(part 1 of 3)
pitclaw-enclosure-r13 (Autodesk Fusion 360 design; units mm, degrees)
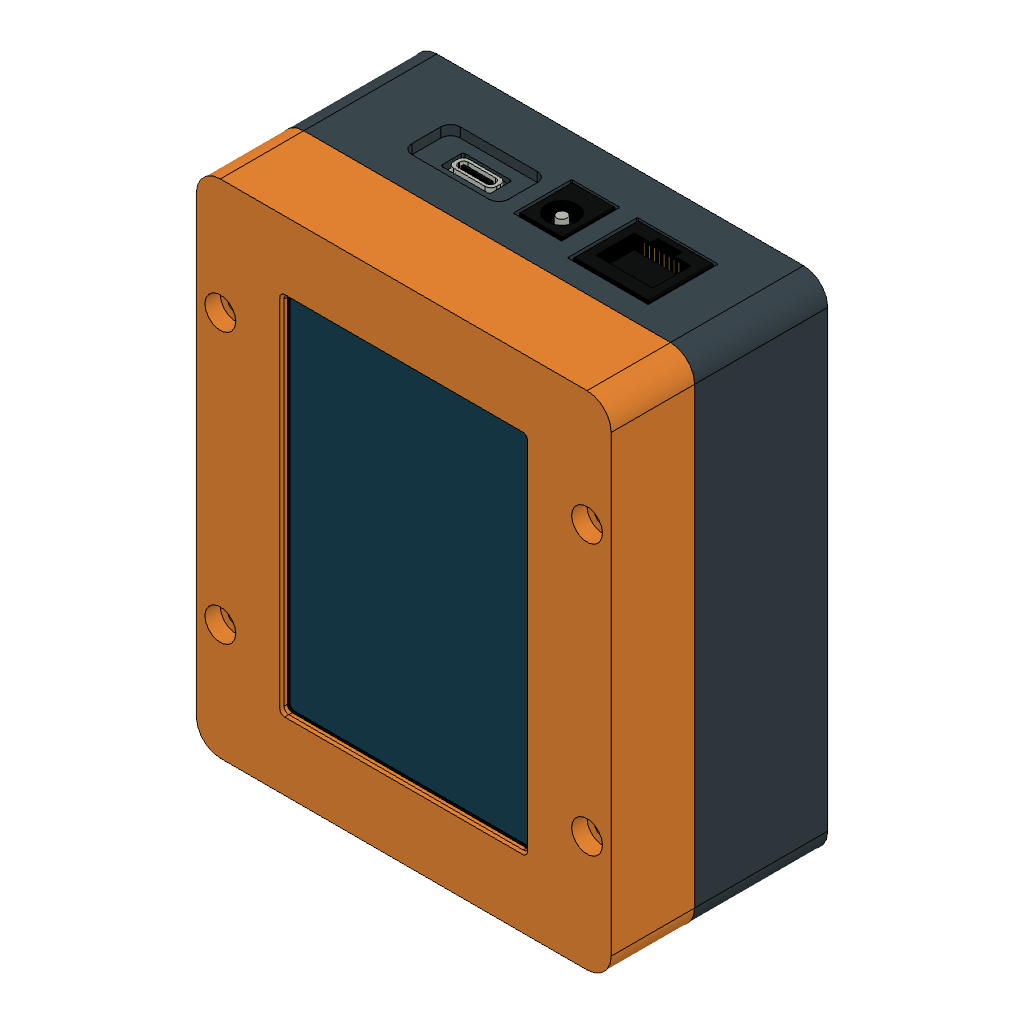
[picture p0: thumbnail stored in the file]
description: Part Number
part number: D_DO-41_SOD81_P10.16mm_Horizontal
part number: R_Axial_DIN0207_L6.3mm_D2.5mm_P7.62mm_Horizontal
part number: PinHeader_1x02_P2.54mm_Vertical
part number: TO-92_Inline_Wide
part number: JST_XH_B2B-XH-A_1x02_P2.50mm_Vertical
part number: JST_XH_B8B-XH-A_1x08_P2.50mm_Vertical
part number: pitclaw-carrier_pad
part number: pitclaw-carrier_silkscreen
part number: pitclaw-carrier_soldermask
parameter "floor_t" = 2.5 comment "PitClaw r8 nominal assembly datum; recheck fit after editing"
parameter "carrier_standoff" = 5 comment "PitClaw r8 nominal assembly datum; recheck fit after editing"
parameter "seam_z" = 27.6 comment "PitClaw r8 nominal assembly datum; recheck fit after editing"
parameter "case_h" = 44.9 comment "PitClaw r8 nominal assembly datum; recheck fit after editing"
parameter "retainer_t" = 2.5 comment "PitClaw r8 nominal assembly datum; recheck fit after editing"
parameter "retainer_top" = 34.4 (= "screen_front_z - screen_mount_depth") comment "PitClaw r8 nominal assembly datum; recheck fit after editing"
parameter "retainer_bottom" = 31.9 (= "retainer_top - retainer_t") comment "PitClaw r8 nominal assembly datum; recheck fit after editing"
parameter "insert_pilot" = 4.2 comment "PitClaw r8 nominal assembly datum; recheck fit after editing"
parameter "insert_depth" = 5 comment "PitClaw r8 nominal assembly datum; recheck fit after editing"
parameter "lip_h" = 2 comment "PitClaw r8 nominal assembly datum; recheck fit after editing"
parameter "bezel_contact_z" = 43.7 comment "Fixed underside of the bezel, on the inactive glass border"
parameter "screen_mount_depth" = 9.3
parameter "screen_interface_t" = 0 comment "Direct glass contact; no assumed soft strip or open air gap"
parameter "screen_front_z" = 43.7 (= "bezel_contact_z - screen_interface_t") comment "Screen front follows the bezel contact face"
parameter "retainer_stop_z" = 34.4 comment "Fixed shell stop: original32.6 plus1.8mm correction"
sketch "Outer shell profile" plane through (0, 0, 0) normal (0, 0, 1) x axis (1, 0, 0)
  line L1 (38, -52) -> (-38, -52)
  line L2 (43, 47) -> (43, -47)
  line L3 (-38, 52) -> (38, 52)
  line L4 (-43, -47) -> (-43, 47)
  arc A1 centre (38, -47) radius 5 clockwise from (43, -47) to (38, -52)
  arc A2 centre (38, 47) radius 5 clockwise from (38, 52) to (43, 47)
  arc A3 centre (-38, 47) radius 5 clockwise from (-43, 47) to (-38, 52)
  arc A4 centre (-38, -47) radius 5 clockwise from (-38, -52) to (-43, -47)
extrude "Extrude1" new body sketch "Outer shell profile" along normal blind 27.6 (= "seam_z") bodies "01 Bottom shell"
sketch "Open cavity profile" plane through (0, 0, 0) normal (0, 0, 1) x axis (1, 0, 0)
  line L1 (38, -49.5) -> (-38, -49.5)
  line L2 (40.5, 47) -> (40.5, -47)
  line L3 (-38, 49.5) -> (38, 49.5)
  line L4 (-40.5, -47) -> (-40.5, 47)
  arc A1 centre (38, -47) radius 2.5 clockwise from (40.5, -47) to (38, -49.5)
  arc A2 centre (38, 47) radius 2.5 clockwise from (38, 49.5) to (40.5, 47)
  arc A3 centre (-38, 47) radius 2.5 clockwise from (-40.5, 47) to (-38, 49.5)
  arc A4 centre (-38, -47) radius 2.5 clockwise from (-38, -49.5) to (-40.5, -47)
extrude "Extrude2" cut sketch "Open cavity profile" blind 27.6 (= "seam_z") from offset 2.5 (= "floor_t")
sketch "Four carrier insert bosses profile" plane through (0, 0, 0) normal (0, 0, 1) x axis (1, 0, 0)
  circle C1 centre (-25.5, -37) radius 4.5
  circle C2 centre (-25.5, 21) radius 4.5
  circle C3 centre (25.5, -37) radius 4.5
  circle C4 centre (25.5, 21) radius 4.5
extrude "Extrude3" add sketch "Four carrier insert bosses profile" blind 5 (= "carrier_standoff") from offset 2.5 (= "floor_t")
sketch "Four case closure columns profile" plane through (0, 0, 0) normal (0, 0, 1) x axis (1, 0, 0)
  circle C1 centre (-38, -28) radius 4.5
  circle C2 centre (-38, 28) radius 4.5
  circle C3 centre (38, -28) radius 4.5
  circle C4 centre (38, 28) radius 4.5
extrude "Extrude4" add sketch "Four case closure columns profile" blind 25.1 (= "seam_z - floor_t") from offset 2.5 (= "floor_t")
sketch "USB recess internal backing profile" plane through (0, 0, 0) normal (0, 1, 0) x axis (1, 0, 0)
  line L1 (22.5, -10.7) -> (6.5, -10.7)
  line L2 (24.5, -18.7) -> (24.5, -12.7)
  line L3 (6.5, -20.7) -> (22.5, -20.7)
  line L4 (4.5, -12.7) -> (4.5, -18.7)
  arc A1 centre (22.5, -12.7) radius 2 clockwise from (22.5, -10.7) to (24.5, -12.7)
  arc A2 centre (22.5, -18.7) radius 2 clockwise from (24.5, -18.7) to (22.5, -20.7)
  arc A3 centre (6.5, -18.7) radius 2 clockwise from (6.5, -20.7) to (4.5, -18.7)
  arc A4 centre (6.5, -12.7) radius 2 clockwise from (4.5, -12.7) to (6.5, -10.7)
extrude "Extrude5" add sketch "USB recess internal backing profile" blind 1.02 from offset 48.5
sketch "Carrier insert pilots profile" plane through (0, 0, 0) normal (0, 0, 1) x axis (1, 0, 0)
  circle C1 centre (-25.5, -37) radius 2.1
  circle C2 centre (-25.5, 21) radius 2.1
  circle C3 centre (25.5, -37) radius 2.1
  circle C4 centre (25.5, 21) radius 2.1
  dimension "d127" diameter C1 = 4.2 (= "insert_pilot")
  dimension "d128" diameter C2 = 4.2 (= "insert_pilot")
  dimension "d129" diameter C3 = 4.2 (= "insert_pilot")
  dimension "d130" diameter C4 = 4.2 (= "insert_pilot")
extrude "Extrude6" cut sketch "Carrier insert pilots profile" blind 5.02 from offset 2.5 (= "floor_t")
sketch "Closure insert pilots profile" plane through (0, 0, 0) normal (0, 0, 1) x axis (1, 0, 0)
  circle C1 centre (-38, -28) radius 2.1
  circle C2 centre (-38, 28) radius 2.1
  circle C3 centre (38, -28) radius 2.1
  circle C4 centre (38, 28) radius 2.1
  dimension "d131" diameter C1 = 4.2 (= "insert_pilot")
  dimension "d132" diameter C2 = 4.2 (= "insert_pilot")
  dimension "d133" diameter C3 = 4.2 (= "insert_pilot")
  dimension "d134" diameter C4 = 4.2 (= "insert_pilot")
extrude "Extrude7" cut sketch "Closure insert pilots profile" blind 5.02 from offset 22.6 (= "seam_z - insert_depth")
sketch "Three probe access holes profile" plane through (0, 0, 0) normal (0, 1, 0) x axis (1, 0, 0)
  circle C1 centre (-17, -11.65) radius 5.25
  circle C2 centre (0, -11.65) radius 5.25
  circle C3 centre (17, -11.65) radius 5.25
extrude "Extrude8" cut sketch "Three probe access holes profile" blind 10 from offset -57
sketch "RJ45 fitted opening profile" plane through (0, 0, 0) normal (0, 1, 0) x axis (1, 0, 0)
  line L1 (-12.325, -8.6) -> (-28.675, -8.6)
  line L2 (-12.125, -22.91) -> (-12.125, -8.8)
  line L3 (-28.675, -23.11) -> (-12.325, -23.11)
  line L4 (-28.875, -8.8) -> (-28.875, -22.91)
  arc A1 centre (-12.325, -8.8) radius 0.2 clockwise from (-12.325, -8.6) to (-12.125, -8.8)
  arc A2 centre (-12.325, -22.91) radius 0.2 clockwise from (-12.125, -22.91) to (-12.325, -23.11)
  arc A3 centre (-28.675, -22.91) radius 0.2 clockwise from (-28.675, -23.11) to (-28.875, -22.91)
  arc A4 centre (-28.675, -8.8) radius 0.2 clockwise from (-28.875, -8.8) to (-28.675, -8.6)
extrude "Extrude9" cut sketch "RJ45 fitted opening profile" blind 10 from offset 47
sketch "Barrel fitted opening profile" plane through (0, 0, 0) normal (0, 1, 0) x axis (1, 0, 0)
  line L1 (1.3, -8.6) -> (-8.3, -8.6)
  line L2 (1.5, -20.5) -> (1.5, -8.8)
  line L3 (-8.3, -20.7) -> (1.3, -20.7)
  line L4 (-8.5, -8.8) -> (-8.5, -20.5)
  arc A1 centre (1.3, -8.8) radius 0.2 clockwise from (1.3, -8.6) to (1.5, -8.8)
  arc A2 centre (1.3, -20.5) radius 0.2 clockwise from (1.5, -20.5) to (1.3, -20.7)
  arc A3 centre (-8.3, -20.5) radius 0.2 clockwise from (-8.3, -20.7) to (-8.5, -20.5)
  arc A4 centre (-8.3, -8.8) radius 0.2 clockwise from (-8.5, -8.8) to (-8.3, -8.6)
extrude "Extrude10" cut sketch "Barrel fitted opening profile" blind 10 from offset 47
sketch "USB fitted shell aperture profile" plane through (0, 0, 0) normal (0, 1, 0) x axis (1, 0, 0)
  line L1 (19.17, -13) -> (9.83, -13)
  line L2 (19.57, -17.3) -> (19.57, -13.4)
  line L3 (9.83, -17.7) -> (19.17, -17.7)
  line L4 (9.43, -13.4) -> (9.43, -17.3)
  arc A1 centre (19.17, -13.4) radius 0.4 clockwise from (19.17, -13) to (19.57, -13.4)
  arc A2 centre (19.17, -17.3) radius 0.4 clockwise from (19.57, -17.3) to (19.17, -17.7)
  arc A3 centre (9.83, -17.3) radius 0.4 clockwise from (9.83, -17.7) to (9.43, -17.3)
  arc A4 centre (9.83, -13.4) radius 0.4 clockwise from (9.43, -13.4) to (9.83, -13)
extrude "Extrude11" cut sketch "USB fitted shell aperture profile" blind 10 from offset 47
sketch "USB shallow external recess profile" plane through (0, 0, 0) normal (0, 1, 0) x axis (1, 0, 0)
  line L1 (22.5, -10.7) -> (6.5, -10.7)
  line L2 (24.5, -18.7) -> (24.5, -12.7)
  line L3 (6.5, -20.7) -> (22.5, -20.7)
  line L4 (4.5, -12.7) -> (4.5, -18.7)
  arc A1 centre (22.5, -12.7) radius 2 clockwise from (22.5, -10.7) to (24.5, -12.7)
  arc A2 centre (22.5, -18.7) radius 2 clockwise from (24.5, -18.7) to (22.5, -20.7)
  arc A3 centre (6.5, -18.7) radius 2 clockwise from (6.5, -20.7) to (4.5, -18.7)
  arc A4 centre (6.5, -12.7) radius 2 clockwise from (4.5, -12.7) to (6.5, -10.7)
extrude "Extrude12" cut sketch "USB shallow external recess profile" blind 2.02 from offset 50
sketch "Hidden carrier edge channel profile" plane through (0, 0, 0) normal (0, 0, 1) x axis (1, 0, 0)
  line L1 (30.5, 49.48) -> (-30.5, 49.48)
  line L2 (30.5, 51) -> (30.5, 49.48)
  line L3 (-30.5, 51) -> (30.5, 51)
  line L4 (-30.5, 49.48) -> (-30.5, 51)
extrude "Extrude13" cut sketch "Hidden carrier edge channel profile" blind 2.9 from offset 7
sketch "Hidden USB PCB edge clearance profile" plane through (0, 0, 0) normal (0, 0, 1) x axis (1, 0, 0)
  line L1 (24.86, 48.48) -> (4.14, 48.48)
  line L2 (24.86, 49.057) -> (24.86, 48.48)
  line L3 (4.14, 49.057) -> (24.86, 49.057)
  line L4 (4.14, 48.48) -> (4.14, 49.057)
extrude "Extrude14" cut sketch "Hidden USB PCB edge clearance profile" blind 3.5 from offset 11.3
sketch "Hidden USB spacer and head clearances profile" plane through (0, 0, 0) normal (0, 0, 1) x axis (1, 0, 0)
  circle C1 centre (6.753, 46.317) radius 2.7
  circle C2 centre (21.993, 46.317) radius 2.7
extrude "Extrude15" cut sketch "Hidden USB spacer and head clearances profile" blind 8.5 from offset 8.3
sketch "Power edge support -28 profile" plane through (0, 0, 0) normal (0, 0, 1) x axis (1, 0, 0)
  line L1 (-25, 49.2) -> (-28, 49.2)
  line L2 (-25, 50.5) -> (-25, 49.2)
  line L3 (-28, 50.5) -> (-25, 50.5)
  line L4 (-28, 49.2) -> (-28, 50.5)
extrude "Extrude16" add sketch "Power edge support -28 profile" blind 5 (= "carrier_standoff") from offset 2.5 (= "floor_t")
sketch "Power edge support 26 profile" plane through (0, 0, 0) normal (0, 0, 1) x axis (1, 0, 0)
  line L1 (29, 49.2) -> (26, 49.2)
  line L2 (29, 50.5) -> (29, 49.2)
  line L3 (26, 50.5) -> (29, 50.5)
  line L4 (26, 49.2) -> (26, 50.5)
extrude "Extrude17" add sketch "Power edge support 26 profile" blind 5 (= "carrier_standoff") from offset 2.5 (= "floor_t")
sketch "Top outer cup profile" plane through (0, 0, 0) normal (0, 0, 1) x axis (1, 0, 0)
  line L1 (38, -52) -> (-38, -52)
  line L2 (43, 47) -> (43, -47)
  line L3 (-38, 52) -> (38, 52)
  line L4 (-43, -47) -> (-43, 47)
  arc A1 centre (38, -47) radius 5 clockwise from (43, -47) to (38, -52)
  arc A2 centre (38, 47) radius 5 clockwise from (38, 52) to (43, 47)
  arc A3 centre (-38, 47) radius 5 clockwise from (-43, 47) to (-38, 52)
  arc A4 centre (-38, -47) radius 5 clockwise from (-38, -52) to (-43, -47)
extrude "Extrude1" new body sketch "Top outer cup profile" blind 17.3 (= "case_h - seam_z") from offset 27.6 (= "seam_z") bodies "02 Top bezel - fitted lip and 4.2mm pilots"
sketch "Top inner cavity profile" plane through (0, 0, 0) normal (0, 0, 1) x axis (1, 0, 0)
  line L1 (38, -49.5) -> (-38, -49.5)
  line L2 (40.5, 47) -> (40.5, -47)
  line L3 (-38, 49.5) -> (38, 49.5)
  line L4 (-40.5, -47) -> (-40.5, 47)
  arc A1 centre (38, -47) radius 2.5 clockwise from (40.5, -47) to (38, -49.5)
  arc A2 centre (38, 47) radius 2.5 clockwise from (38, 49.5) to (40.5, 47)
  arc A3 centre (-38, 47) radius 2.5 clockwise from (-40.5, 47) to (-38, 49.5)
  arc A4 centre (-38, -47) radius 2.5 clockwise from (-38, -49.5) to (-40.5, -47)
extrude "Extrude2" cut sketch "Top inner cavity profile" blind 14.32 (= "case_h - 3 mm - seam_z + 0.02 mm") from offset 27.58 (= "seam_z - 0.02 mm")
sketch "Locating lip connecting shoulder profile" plane through (0, 0, 0) normal (0, 0, 1) x axis (1, 0, 0)
  line L1 (38, -52) -> (-38, -52)
  line L2 (43, 47) -> (43, -47)
  line L3 (-38, 52) -> (38, 52)
  line L4 (-43, -47) -> (-43, 47)
  line L5 (35, -48) -> (-35, -48)
  line L6 (39, 44) -> (39, -44)
  line L7 (-35, 48) -> (35, 48)
  line L8 (-39, -44) -> (-39, 44)
  arc A1 centre (38, -47) radius 5 clockwise from (43, -47) to (38, -52)
  arc A2 centre (38, 47) radius 5 clockwise from (38, 52) to (43, 47)
  arc A3 centre (-38, 47) radius 5 clockwise from (-43, 47) to (-38, 52)
  arc A4 centre (-38, -47) radius 5 clockwise from (-38, -52) to (-43, -47)
  arc A5 centre (35, -44) radius 4 clockwise from (39, -44) to (35, -48)
  arc A6 centre (35, 44) radius 4 clockwise from (35, 48) to (39, 44)
  arc A7 centre (-35, 44) radius 4 clockwise from (-39, 44) to (-35, 48)
  arc A8 centre (-35, -44) radius 4 clockwise from (-35, -48) to (-39, -44)
extrude "Extrude3" add sketch "Locating lip connecting shoulder profile" blind 1 from offset 27.6 (= "seam_z")
sketch "Locating lip profile" plane through (0, 0, 0) normal (0, 0, 1) x axis (1, 0, 0)
  line L1 (38.2, -49.2) -> (-38.2, -49.2)
  line L2 (40.2, 47.2) -> (40.2, -47.2)
  line L3 (-38.2, 49.2) -> (38.2, 49.2)
  line L4 (-40.2, -47.2) -> (-40.2, 47.2)
  line L5 (38, -48) -> (-38, -48)
  line L6 (39, 47) -> (39, -47)
  line L7 (-38, 48) -> (38, 48)
  line L8 (-39, -47) -> (-39, 47)
  arc A1 centre (38.2, -47.2) radius 2 clockwise from (40.2, -47.2) to (38.2, -49.2)
  arc A2 centre (38.2, 47.2) radius 2 clockwise from (38.2, 49.2) to (40.2, 47.2)
  arc A3 centre (-38.2, 47.2) radius 2 clockwise from (-40.2, 47.2) to (-38.2, 49.2)
  arc A4 centre (-38.2, -47.2) radius 2 clockwise from (-38.2, -49.2) to (-40.2, -47.2)
  arc A5 centre (38, -47) radius 1 clockwise from (39, -47) to (38, -48)
  arc A6 centre (38, 47) radius 1 clockwise from (38, 48) to (39, 47)
  arc A7 centre (-38, 47) radius 1 clockwise from (-39, 47) to (-38, 48)
  arc A8 centre (-38, -47) radius 1 clockwise from (-38, -48) to (-39, -47)
extrude "Extrude4" add sketch "Locating lip profile" blind 2.02 (= "lip_h + 0.02 mm") from offset 25.6 (= "seam_z - lip_h")
sketch "Lip relief around closure columns profile" plane through (0, 0, 0) normal (0, 0, 1) x axis (1, 0, 0)
  circle C1 centre (-38, -28) radius 5
  circle C2 centre (-38, 28) radius 5
  circle C3 centre (38, -28) radius 5
  circle C4 centre (38, 28) radius 5
extrude "Extrude5" cut sketch "Lip relief around closure columns profile" blind 2.02 (= "lip_h + 0.02 mm") from offset 25.58 (= "seam_z - lip_h - 0.02 mm")
sketch "Four independent closure columns profile" plane through (0, 0, 0) normal (0, 0, 1) x axis (1, 0, 0)
  circle C1 centre (-38, -28) radius 4.5
  circle C2 centre (-38, 28) radius 4.5
  circle C3 centre (38, -28) radius 4.5
  circle C4 centre (38, 28) radius 4.5
extrude "Extrude6" add sketch "Four independent closure columns profile" blind 17.3 (= "case_h - seam_z") from offset 27.6 (= "seam_z")
sketch "Four display retainer hard stops profile" plane through (0, 0, 0) normal (0, 0, 1) x axis (1, 0, 0)
  circle C1 centre (-35.5, -40) radius 4.5
  circle C2 centre (-35.5, 40) radius 4.5
  circle C3 centre (35.5, -40) radius 4.5
  circle C4 centre (35.5, 40) radius 4.5
extrude "Extrude7" add sketch "Four display retainer hard stops profile" blind 10.5 (= "case_h - retainer_stop_z") from offset 34.4 (= "retainer_stop_z")
sketch "Display body and glass pocket profile" plane through (0, 0, 0) normal (0, 0, 1) x axis (1, 0, 0)
  line L1 (29.1, -46.6) -> (-29.1, -46.6)
  line L2 (30.6, 45.1) -> (30.6, -45.1)
  line L3 (-29.1, 46.6) -> (29.1, 46.6)
  line L4 (-30.6, -45.1) -> (-30.6, 45.1)
  arc A1 centre (29.1, -45.1) radius 1.5 clockwise from (30.6, -45.1) to (29.1, -46.6)
  arc A2 centre (29.1, 45.1) radius 1.5 clockwise from (29.1, 46.6) to (30.6, 45.1)
  arc A3 centre (-29.1, 45.1) radius 1.5 clockwise from (-30.6, 45.1) to (-29.1, 46.6)
  arc A4 centre (-29.1, -45.1) radius 1.5 clockwise from (-29.1, -46.6) to (-30.6, -45.1)
extrude "Extrude8" cut sketch "Display body and glass pocket profile" blind 16.12 (= "bezel_contact_z - seam_z + 0.02 mm") from offset 27.58 (= "seam_z - 0.02 mm")
sketch "Active display window profile" plane through (0, 0, 0) normal (0, 0, 1) x axis (1, 0, 0)
  line L1 (24.3, -37.55) -> (-24.3, -37.55)
  line L2 (25.3, 36.55) -> (25.3, -36.55)
  line L3 (-24.3, 37.55) -> (24.3, 37.55)
  line L4 (-25.3, -36.55) -> (-25.3, 36.55)
  arc A1 centre (24.3, -36.55) radius 1 clockwise from (25.3, -36.55) to (24.3, -37.55)
  arc A2 centre (24.3, 36.55) radius 1 clockwise from (24.3, 37.55) to (25.3, 36.55)
  arc A3 centre (-24.3, 36.55) radius 1 clockwise from (-25.3, 36.55) to (-24.3, 37.55)
  arc A4 centre (-24.3, -36.55) radius 1 clockwise from (-24.3, -37.55) to (-25.3, -36.55)
extrude "Extrude9" cut sketch "Active display window profile" blind 1.24 (= "case_h - bezel_contact_z + 0.04 mm") from offset 43.68 (= "bezel_contact_z - 0.02 mm")
work_plane "WorkPlane1" AlongDistance 44.4 ExtraOffset 0
sketch "Front window bevel start profile" plane through (0, 0, 44.4) normal (0, 0, 1) x axis (1, 0, 0)
  line L1 (24.3, -37.55) -> (-24.3, -37.55)
  line L2 (25.3, 36.55) -> (25.3, -36.55)
  line L3 (-24.3, 37.55) -> (24.3, 37.55)
  line L4 (-25.3, -36.55) -> (-25.3, 36.55)
  arc A1 centre (24.3, -36.55) radius 1 clockwise from (25.3, -36.55) to (24.3, -37.55)
  arc A2 centre (24.3, 36.55) radius 1 clockwise from (24.3, 37.55) to (25.3, 36.55)
  arc A3 centre (-24.3, 36.55) radius 1 clockwise from (-25.3, 36.55) to (-24.3, 37.55)
  arc A4 centre (-24.3, -36.55) radius 1 clockwise from (-24.3, -37.55) to (-25.3, -36.55)
work_plane "WorkPlane2" AlongDistance 44.92 ExtraOffset 0
sketch "Front window bevel end profile" plane through (0, 0, 44.92) normal (0, 0, 1) x axis (1, 0, 0)
  line L1 (24.6695, -37.9255) -> (-24.6695, -37.9255)
  line L2 (25.6795, 36.9155) -> (25.6795, -36.9155)
  line L3 (-24.6695, 37.9255) -> (24.6695, 37.9255)
  line L4 (-25.6795, -36.9155) -> (-25.6795, 36.9155)
  arc A1 centre (24.6695, -36.9155) radius 1.01 clockwise from (25.6795, -36.9155) to (24.6695, -37.9255)
  arc A2 centre (24.6695, 36.9155) radius 1.01 clockwise from (24.6695, 37.9255) to (25.6795, 36.9155)
  arc A3 centre (-24.6695, 36.9155) radius 1.01 clockwise from (-25.6795, 36.9155) to (-24.6695, 37.9255)
  arc A4 centre (-24.6695, -36.9155) radius 1.01 clockwise from (-24.6695, -37.9255) to (-25.6795, -36.9155)
loft "Loft1" sketch "Front window bevel start profile" + "Front window bevel end profile"
sketch "Case screw clearance holes profile" plane through (0, 0, 0) normal (0, 0, 1) x axis (1, 0, 0)
  circle C1 centre (-38, -28) radius 1.7
  circle C2 centre (-38, 28) radius 1.7
  circle C3 centre (38, -28) radius 1.7
  circle C4 centre (38, 28) radius 1.7
extrude "Extrude10" cut sketch "Case screw clearance holes profile" blind 17.34 (= "case_h - seam_z + 0.04 mm") from offset 27.58 (= "seam_z - 0.02 mm")
sketch "Case screw head recesses profile" plane through (0, 0, 0) normal (0, 0, 1) x axis (1, 0, 0)
  circle C1 centre (-38, -28) radius 3.2
  circle C2 centre (-38, 28) radius 3.2
  circle C3 centre (38, -28) radius 3.2
  circle C4 centre (38, 28) radius 3.2
extrude "Extrude11" cut sketch "Case screw head recesses profile" blind 3.22 from offset 41.7 (= "case_h - 3.2 mm")
sketch "Four retainer insert pilots profile" plane through (0, 0, 0) normal (0, 0, 1) x axis (1, 0, 0)
  circle C1 centre (-35.5, -40) radius 2.1
  circle C2 centre (-35.5, 40) radius 2.1
  circle C3 centre (35.5, -40) radius 2.1
  circle C4 centre (35.5, 40) radius 2.1
  dimension "d135" diameter C1 = 4.2 (= "insert_pilot")
  dimension "d136" diameter C2 = 4.2 (= "insert_pilot")
  dimension "d137" diameter C3 = 4.2 (= "insert_pilot")
  dimension "d138" diameter C4 = 4.2 (= "insert_pilot")
extrude "Extrude12" cut sketch "Four retainer insert pilots profile" blind 5.02 (= "insert_depth + 0.02 mm") from offset 34.38 (= "retainer_stop_z - 0.02 mm")
sketch "Retainer insertion relief profile" plane through (0, 0, 0) normal (0, 0, 1) x axis (1, 0, 0)
  line L1 (34.4, -48.5) -> (-34.4, -48.5)
  line L2 (35.4, 47.5) -> (35.4, -47.5)
  line L3 (-34.4, 48.5) -> (34.4, 48.5)
  line L4 (-35.4, -47.5) -> (-35.4, 47.5)
  arc A1 centre (34.4, -47.5) radius 1 clockwise from (35.4, -47.5) to (34.4, -48.5)
  arc A2 centre (34.4, 47.5) radius 1 clockwise from (34.4, 48.5) to (35.4, 47.5)
  arc A3 centre (-34.4, 47.5) radius 1 clockwise from (-35.4, 47.5) to (-34.4, 48.5)
  arc A4 centre (-34.4, -47.5) radius 1 clockwise from (-34.4, -48.5) to (-35.4, -47.5)
extrude "Extrude13" cut sketch "Retainer insertion relief profile" blind 3.04 (= "lip_h + 1.04 mm") from offset 25.58 (= "seam_z - lip_h - 0.02 mm")
sketch "Four anchor pad insertion reliefs profile" plane through (0, 0, 0) normal (0, 0, 1) x axis (1, 0, 0)
  circle C1 centre (-35.5, -40) radius 5
  circle C2 centre (-35.5, 40) radius 5
  circle C3 centre (35.5, -40) radius 5
  circle C4 centre (35.5, 40) radius 5
extrude "Extrude14" cut sketch "Four anchor pad insertion reliefs profile" blind 3.04 (= "lip_h + 1.04 mm") from offset 25.58 (= "seam_z - lip_h - 0.02 mm")
sketch "Thin perimeter frame profile" plane through (0, 0, 0) normal (0, 0, 1) x axis (1, 0, 0)
  line L1 (34, -48) -> (-34, -48)
  line L2 (35, 47) -> (35, -47)
  line L3 (-34, 48) -> (34, 48)
  line L4 (-35, -47) -> (-35, 47)
  line L5 (30, -46.4) -> (-30, -46.4)
  line L6 (30.4, 46) -> (30.4, -46)
  line L7 (-30, 46.4) -> (30, 46.4)
  line L8 (-30.4, -46) -> (-30.4, 46)
  arc A1 centre (34, -47) radius 1 clockwise from (35, -47) to (34, -48)
  arc A2 centre (34, 47) radius 1 clockwise from (34, 48) to (35, 47)
  arc A3 centre (-34, 47) radius 1 clockwise from (-35, 47) to (-34, 48)
  arc A4 centre (-34, -47) radius 1 clockwise from (-34, -48) to (-35, -47)
  arc A5 centre (30, -46) radius 0.4 clockwise from (30.4, -46) to (30, -46.4)
  arc A6 centre (30, 46) radius 0.4 clockwise from (30, 46.4) to (30.4, 46)
  arc A7 centre (-30, 46) radius 0.4 clockwise from (-30.4, 46) to (-30, 46.4)
  arc A8 centre (-30, -46) radius 0.4 clockwise from (-30, -46.4) to (-30.4, -46)
extrude "Extrude1" new body sketch "Thin perimeter frame profile" blind 2.5 (= "retainer_t") from offset 31.9 (= "retainer_bottom") bodies "03 WT32 retainer - four anchors"
sketch "Four OEM mounting pads and rail ties profile" plane through (0, 0, 0) normal (0, 0, 1) x axis (1, 0, 0)
  line L1 (-26.9131, -36.5209) -> (-32.3045, -38.7402)
  line L2 (-32.3045, -40.2198) -> (-26.9131, -42.4391)
  line L3 (-26.9131, 38.6191) -> (-32.3045, 36.3998)
  line L4 (-32.3045, 34.9202) -> (-26.9131, 32.7009)
  line L5 (32.3045, -38.7402) -> (26.9131, -36.5209)
  line L6 (26.9131, -42.4391) -> (32.3045, -40.2198)
  line L7 (32.3045, 36.3998) -> (26.9131, 38.6191)
  line L8 (26.9131, 32.7009) -> (32.3045, 34.9202)
  arc A1 centre (-25.695, -39.48) radius 3.2 clockwise from (-26.9131, -36.5209) to (-26.9131, -42.4391)
  arc A2 centre (-32, -39.48) radius 0.8 clockwise from (-32.3045, -40.2198) to (-32.3045, -38.7402)
  arc A3 centre (-25.695, 35.66) radius 3.2 clockwise from (-26.9131, 38.6191) to (-26.9131, 32.7009)
  arc A4 centre (-32, 35.66) radius 0.8 clockwise from (-32.3045, 34.9202) to (-32.3045, 36.3998)
  arc A5 centre (32, -39.48) radius 0.8 clockwise from (32.3045, -38.7402) to (32.3045, -40.2198)
  arc A6 centre (25.695, -39.48) radius 3.2 clockwise from (26.9131, -42.4391) to (26.9131, -36.5209)
  arc A7 centre (32, 35.66) radius 0.8 clockwise from (32.3045, 36.3998) to (32.3045, 34.9202)
  arc A8 centre (25.695, 35.66) radius 3.2 clockwise from (26.9131, 32.7009) to (26.9131, 38.6191)
extrude "Extrude2" add sketch "Four OEM mounting pads and rail ties profile" blind 2.5 (= "retainer_t") from offset 31.9 (= "retainer_bottom")
sketch "Four case anchor pads profile" plane through (0, 0, 0) normal (0, 0, 1) x axis (1, 0, 0)
  circle C1 centre (-35.5, -40) radius 4.5
  circle C2 centre (-35.5, 40) radius 4.5
  circle C3 centre (35.5, -40) radius 4.5
  circle C4 centre (35.5, 40) radius 4.5
extrude "Extrude3" add sketch "Four case anchor pads profile" blind 2.5 (= "retainer_t") from offset 31.9 (= "retainer_bottom")
sketch "Closure column scallops profile" plane through (0, 0, 0) normal (0, 0, 1) x axis (1, 0, 0)
  circle C1 centre (-38, -28) radius 5
  circle C2 centre (-38, 28) radius 5
  circle C3 centre (38, -28) radius 5
  circle C4 centre (38, 28) radius 5
extrude "Extrude4" cut sketch "Closure column scallops profile" blind 2.54 (= "retainer_t + 0.04 mm") from offset 31.88 (= "retainer_bottom - 0.02 mm")
sketch "WT32 rear blind boss screw clearances profile" plane through (0, 0, 0) normal (0, 0, 1) x axis (1, 0, 0)
  circle C1 centre (-25.695, -39.48) radius 1.4
  circle C2 centre (-25.695, 35.66) radius 1.4
  circle C3 centre (25.695, -39.48) radius 1.4
  circle C4 centre (25.695, 35.66) radius 1.4
extrude "Extrude5" cut sketch "WT32 rear blind boss screw clearances profile" blind 2.54 (= "retainer_t + 0.04 mm") from offset 31.88 (= "retainer_bottom - 0.02 mm")
sketch "Four M3 anchor screw clearances profile" plane through (0, 0, 0) normal (0, 0, 1) x axis (1, 0, 0)
  circle C1 centre (-35.5, -40) radius 1.7
  circle C2 centre (-35.5, 40) radius 1.7
  circle C3 centre (35.5, -40) radius 1.7
  circle C4 centre (35.5, 40) radius 1.7
extrude "Extrude6" cut sketch "Four M3 anchor screw clearances profile" blind 2.54 (= "retainer_t + 0.04 mm") from offset 31.88 (= "retainer_bottom - 0.02 mm")
sketch "Nominal carrier outline profile" plane through (0, 0, 0) normal (0, 0, 1) x axis (1, 0, 0)
  line L1 (30, -41.5) -> (-30, -41.5)
  line L2 (30, 50.5) -> (30, -41.5)
  line L3 (-30, 50.5) -> (30, 50.5)
  line L4 (-30, -41.5) -> (-30, 50.5)
extrude "Extrude1" new body sketch "Nominal carrier outline profile" blind 1.6 from offset 7.5 bodies "Carrier PCB - placed components omitted"
sketch "Carrier mounting holes profile" plane through (0, 0, 0) normal (0, 0, 1) x axis (1, 0, 0)
  circle C1 centre (-25.5, -37) radius 1.6
  circle C2 centre (-25.5, 21) radius 1.6
  circle C3 centre (25.5, -37) radius 1.6
  circle C4 centre (25.5, 21) radius 1.6
extrude "Extrude2" cut sketch "Carrier mounting holes profile" blind 1.64 from offset 7.48
sketch "Display glass outline profile" plane through (0, 0, 0) normal (0, 0, 1) x axis (1, 0, 0)
  line L1 (28.5, -46) -> (-28.5, -46)
  line L2 (30, 44.5) -> (30, -44.5)
  line L3 (-28.5, 46) -> (28.5, 46)
  line L4 (-30, -44.5) -> (-30, 44.5)
  arc A1 centre (28.5, -44.5) radius 1.5 clockwise from (30, -44.5) to (28.5, -46)
  arc A2 centre (28.5, 44.5) radius 1.5 clockwise from (28.5, 46) to (30, 44.5)
  arc A3 centre (-28.5, 44.5) radius 1.5 clockwise from (-30, 44.5) to (-28.5, 46)
  arc A4 centre (-28.5, -44.5) radius 1.5 clockwise from (-28.5, -46) to (-30, -44.5)
extrude "Extrude1" new body sketch "Display glass outline profile" blind 1.45 from offset 42.25 (= "screen_front_z - 1.45 mm") bodies "WT32 nominal envelope - sample verification required"
sketch "Active display area profile" plane through (0, 0, 0) normal (0, 0, 1) x axis (1, 0, 0)
  line L1 (23.78, -37.02) -> (-23.78, -37.02)
  line L2 (24.78, 36.02) -> (24.78, -36.02)
  line L3 (-23.78, 37.02) -> (23.78, 37.02)
  line L4 (-24.78, -36.02) -> (-24.78, 36.02)
  arc A1 centre (23.78, -36.02) radius 1 clockwise from (24.78, -36.02) to (23.78, -37.02)
  arc A2 centre (23.78, 36.02) radius 1 clockwise from (23.78, 37.02) to (24.78, 36.02)
  arc A3 centre (-23.78, 36.02) radius 1 clockwise from (-24.78, 36.02) to (-23.78, 37.02)
  arc A4 centre (-23.78, -36.02) radius 1 clockwise from (-23.78, -37.02) to (-24.78, -36.02)
extrude "Extrude2" new body sketch "Active display area profile" blind 0.03 from offset 43.7 (= "screen_front_z")
sketch "Display frame envelope profile" plane through (0, 0, 0) normal (0, 0, 1) x axis (1, 0, 0)
  line L1 (28.5, -46) -> (-28.5, -46)
  line L2 (30, 44.5) -> (30, -44.5)
  line L3 (-28.5, 46) -> (28.5, 46)
  line L4 (-30, -44.5) -> (-30, 44.5)
  line L5 (26, -41) -> (-26, -41)
  line L6 (26.5, 40.5) -> (26.5, -40.5)
  line L7 (-26, 41) -> (26, 41)
  line L8 (-26.5, -40.5) -> (-26.5, 40.5)
  arc A1 centre (28.5, -44.5) radius 1.5 clockwise from (30, -44.5) to (28.5, -46)
  arc A2 centre (28.5, 44.5) radius 1.5 clockwise from (28.5, 46) to (30, 44.5)
  arc A3 centre (-28.5, 44.5) radius 1.5 clockwise from (-30, 44.5) to (-28.5, 46)
  arc A4 centre (-28.5, -44.5) radius 1.5 clockwise from (-28.5, -46) to (-30, -44.5)
  arc A5 centre (26, -40.5) radius 0.5 clockwise from (26.5, -40.5) to (26, -41)
  arc A6 centre (26, 40.5) radius 0.5 clockwise from (26, 41) to (26.5, 40.5)
  arc A7 centre (-26, 40.5) radius 0.5 clockwise from (-26.5, 40.5) to (-26, 41)
  arc A8 centre (-26, -40.5) radius 0.5 clockwise from (-26, -41) to (-26.5, -40.5)
extrude "Extrude3" new body sketch "Display frame envelope profile" blind 3.35 from offset 38.9 (= "screen_front_z - 4.8 mm")
sketch "Display rear PCB envelope profile" plane through (0, 0, 0) normal (0, 0, 1) x axis (1, 0, 0)
  line L1 (24, -35) -> (-24, -35)
  line L2 (24, 35) -> (24, -35)
  line L3 (-24, 35) -> (24, 35)
  line L4 (-24, -35) -> (-24, 35)
extrude "Extrude4" new body sketch "Display rear PCB envelope profile" blind 1.6 from offset 34.4 (= "screen_front_z - screen_mount_depth")
sketch "Four rear mounting boss envelopes profile" plane through (0, 0, 0) normal (0, 0, 1) x axis (1, 0, 0)
  circle C1 centre (-25.695, -39.48) radius 2.9
  circle C2 centre (-25.695, 35.66) radius 2.9
  circle C3 centre (25.695, -39.48) radius 2.9
  circle C4 centre (25.695, 35.66) radius 2.9
extrude "Extrude5" new body sketch "Four rear mounting boss envelopes profile" blind 4.5 (= "screen_mount_depth - 4.8 mm") from offset 34.4 (= "retainer_top")
combine "Combine1"
base_feature "Base Feature1"
base_feature "Base Feature1"
base_feature "Base Feature1"
base_feature "Base Feature1"
base_feature "Base Feature1"
base_feature "Base Feature1"
base_feature "Base Feature1"
base_feature "Base Feature1"
base_feature "Base Feature1"
base_feature "Base Feature1"
base_feature "Base Feature1"
base_feature "Base Feature1"
base_feature "Base Feature1"
mirror "Mirror1" mirrorStitchTolerance 0.01 bodies "01 Bottom shell - fitted guides and 4.2mm pilots"
remove_body "RemoveBody1"
sketch "C1 electrolytic sleeve profile" plane through (0, 0, 0) normal (0, 0, 1) x axis (1, 0, 0)
  circle C1 centre (-15.5, 17.5) radius 5
extrude "Extrude1" new body sketch "C1 electrolytic sleeve profile" blind 12.5 from offset 9.4 bodies "C1 electrolytic sleeve"
sketch "C1 aluminum top profile" plane through (0, 0, 0) normal (0, 0, 1) x axis (1, 0, 0)
  circle C1 centre (-15.5, 17.5) radius 4.8
extrude "Extrude2" new body sketch "C1 aluminum top profile" blind 0.16 from offset 21.75 bodies "C1 aluminum top"
sketch "C1 leads profile" plane through (0, 0, 0) normal (0, 0, 1) x axis (1, 0, 0)
  circle C1 centre (-13, 17.5) radius 0.3
  circle C2 centre (-18, 17.5) radius 0.3
extrude "Extrude3" new body sketch "C1 leads profile" blind 3.5 from offset 6.5 bodies "C1 leads", "C1 leads (1)"
sketch "C3 electrolytic sleeve profile" plane through (0, 0, 0) normal (0, 0, 1) x axis (1, 0, 0)
  circle C1 centre (-25, -27) radius 4
extrude "Extrude1" new body sketch "C3 electrolytic sleeve profile" blind 11.5 from offset 9.4 bodies "C3 electrolytic sleeve"
sketch "C3 aluminum top profile" plane through (0, 0, 0) normal (0, 0, 1) x axis (1, 0, 0)
  circle C1 centre (-25, -27) radius 3.8
extrude "Extrude2" new body sketch "C3 aluminum top profile" blind 0.16 from offset 20.75 bodies "C3 aluminum top"
sketch "C3 leads profile" plane through (0, 0, 0) normal (0, 0, 1) x axis (1, 0, 0)
  circle C1 centre (-23.25, -27) radius 0.3
  circle C2 centre (-26.75, -27) radius 0.3
extrude "Extrude3" new body sketch "C3 leads profile" blind 3.5 from offset 6.5 bodies "C3 leads", "C3 leads (1)"
sketch "C2 ceramic body profile" plane through (0, 0, 0) normal (0, 0, 1) x axis (1, 0, 0)
  line L1 (14.15, 22.25) -> (10.85, 22.25)
  line L2 (14.5, 24.4) -> (14.5, 22.6)
  line L3 (10.85, 24.75) -> (14.15, 24.75)
  line L4 (10.5, 22.6) -> (10.5, 24.4)
  arc A1 centre (14.15, 22.6) radius 0.35 clockwise from (14.5, 22.6) to (14.15, 22.25)
  arc A2 centre (14.15, 24.4) radius 0.35 clockwise from (14.15, 24.75) to (14.5, 24.4)
  arc A3 centre (10.85, 24.4) radius 0.35 clockwise from (10.5, 24.4) to (10.85, 24.75)
  arc A4 centre (10.85, 22.6) radius 0.35 clockwise from (10.85, 22.25) to (10.5, 22.6)
extrude "Extrude1" new body sketch "C2 ceramic body profile" blind 4 from offset 10.6 bodies "C2 ceramic body"
sketch "C2 leads profile" plane through (0, 0, 0) normal (0, 0, 1) x axis (1, 0, 0)
  circle C1 centre (15, 23.5) radius 0.275
  circle C2 centre (10, 23.5) radius 0.275
extrude "Extrude2" new body sketch "C2 leads profile" blind 4.2 from offset 6.5 bodies "C2 leads", "C2 leads (1)"
sketch "C4 ceramic body profile" plane through (0, 0, 0) normal (0, 0, 1) x axis (1, 0, 0)
  line L1 (0.4, 29) -> (-1.4, 29)
  line L2 (0.75, 32.65) -> (0.75, 29.35)
  line L3 (-1.4, 33) -> (0.4, 33)
  line L4 (-1.75, 29.35) -> (-1.75, 32.65)
  arc A1 centre (0.4, 29.35) radius 0.35 clockwise from (0.75, 29.35) to (0.4, 29)
  arc A2 centre (0.4, 32.65) radius 0.35 clockwise from (0.4, 33) to (0.75, 32.65)
  arc A3 centre (-1.4, 32.65) radius 0.35 clockwise from (-1.75, 32.65) to (-1.4, 33)
  arc A4 centre (-1.4, 29.35) radius 0.35 clockwise from (-1.4, 29) to (-1.75, 29.35)
extrude "Extrude1" new body sketch "C4 ceramic body profile" blind 4 from offset 10.6 bodies "C4 ceramic body"
sketch "C4 leads profile" plane through (0, 0, 0) normal (0, 0, 1) x axis (1, 0, 0)
  circle C1 centre (-0.5, 28.5) radius 0.275
  circle C2 centre (-0.5, 33.5) radius 0.275
extrude "Extrude2" new body sketch "C4 leads profile" blind 4.2 from offset 6.5 bodies "C4 leads", "C4 leads (1)"
sketch "C10 ceramic body profile" plane through (0, 0, 0) normal (0, 0, 1) x axis (1, 0, 0)
  line L1 (14.15, -4.75) -> (10.85, -4.75)
  line L2 (14.5, -2.6) -> (14.5, -4.4)
  line L3 (10.85, -2.25) -> (14.15, -2.25)
  line L4 (10.5, -4.4) -> (10.5, -2.6)
  arc A1 centre (14.15, -4.4) radius 0.35 clockwise from (14.5, -4.4) to (14.15, -4.75)
  arc A2 centre (14.15, -2.6) radius 0.35 clockwise from (14.15, -2.25) to (14.5, -2.6)
  arc A3 centre (10.85, -2.6) radius 0.35 clockwise from (10.5, -2.6) to (10.85, -2.25)
  arc A4 centre (10.85, -4.4) radius 0.35 clockwise from (10.85, -4.75) to (10.5, -4.4)
extrude "Extrude1" new body sketch "C10 ceramic body profile" blind 4 from offset 10.6 bodies "C10 ceramic body"
sketch "C10 leads profile" plane through (0, 0, 0) normal (0, 0, 1) x axis (1, 0, 0)
  circle C1 centre (15, -3.5) radius 0.275
  circle C2 centre (10, -3.5) radius 0.275
extrude "Extrude2" new body sketch "C10 leads profile" blind 4.2 from offset 6.5 bodies "C10 leads", "C10 leads (1)"
sketch "C11 ceramic body profile" plane through (0, 0, 0) normal (0, 0, 1) x axis (1, 0, 0)
  line L1 (14.15, 3.25) -> (10.85, 3.25)
  line L2 (14.5, 5.4) -> (14.5, 3.6)
  line L3 (10.85, 5.75) -> (14.15, 5.75)
  line L4 (10.5, 3.6) -> (10.5, 5.4)
  arc A1 centre (14.15, 3.6) radius 0.35 clockwise from (14.5, 3.6) to (14.15, 3.25)
  arc A2 centre (14.15, 5.4) radius 0.35 clockwise from (14.15, 5.75) to (14.5, 5.4)
  arc A3 centre (10.85, 5.4) radius 0.35 clockwise from (10.5, 5.4) to (10.85, 5.75)
  arc A4 centre (10.85, 3.6) radius 0.35 clockwise from (10.85, 3.25) to (10.5, 3.6)
extrude "Extrude1" new body sketch "C11 ceramic body profile" blind 4 from offset 10.6 bodies "C11 ceramic body"
sketch "C11 leads profile" plane through (0, 0, 0) normal (0, 0, 1) x axis (1, 0, 0)
  circle C1 centre (15, 4.5) radius 0.275
  circle C2 centre (10, 4.5) radius 0.275
extrude "Extrude2" new body sketch "C11 leads profile" blind 4.2 from offset 6.5 bodies "C11 leads", "C11 leads (1)"
sketch "C12 ceramic body profile" plane through (0, 0, 0) normal (0, 0, 1) x axis (1, 0, 0)
  line L1 (14.15, 11.25) -> (10.85, 11.25)
  line L2 (14.5, 13.4) -> (14.5, 11.6)
  line L3 (10.85, 13.75) -> (14.15, 13.75)
  line L4 (10.5, 11.6) -> (10.5, 13.4)
  arc A1 centre (14.15, 11.6) radius 0.35 clockwise from (14.5, 11.6) to (14.15, 11.25)
  arc A2 centre (14.15, 13.4) radius 0.35 clockwise from (14.15, 13.75) to (14.5, 13.4)
  arc A3 centre (10.85, 13.4) radius 0.35 clockwise from (10.5, 13.4) to (10.85, 13.75)
  arc A4 centre (10.85, 11.6) radius 0.35 clockwise from (10.85, 11.25) to (10.5, 11.6)
extrude "Extrude1" new body sketch "C12 ceramic body profile" blind 4 from offset 10.6 bodies "C12 ceramic body"
sketch "C12 leads profile" plane through (0, 0, 0) normal (0, 0, 1) x axis (1, 0, 0)
  circle C1 centre (15, 12.5) radius 0.275
  circle C2 centre (10, 12.5) radius 0.275
extrude "Extrude2" new body sketch "C12 leads profile" blind 4.2 from offset 6.5 bodies "C12 leads", "C12 leads (1)"
sketch "K1 relay case profile" plane through (0, 0, 0) normal (0, 0, 1) x axis (1, 0, 0)
  line L1 (0.75, 3.5) -> (-9.05, 3.5)
  line L2 (1, 23.55) -> (1, 3.75)
  line L3 (-9.05, 23.8) -> (0.75, 23.8)
  line L4 (-9.3, 3.75) -> (-9.3, 23.55)
  arc A1 centre (0.75, 3.75) radius 0.25 clockwise from (1, 3.75) to (0.75, 3.5)
  arc A2 centre (0.75, 23.55) radius 0.25 clockwise from (0.75, 23.8) to (1, 23.55)
  arc A3 centre (-9.05, 23.55) radius 0.25 clockwise from (-9.3, 23.55) to (-9.05, 23.8)
  arc A4 centre (-9.05, 3.75) radius 0.25 clockwise from (-9.05, 3.5) to (-9.3, 3.75)
extrude "Extrude1" new body sketch "K1 relay case profile" blind 15.8 from offset 9.5 bodies "K1 relay case"
sketch "K1 leads profile" plane through (0, 0, 0) normal (0, 0, 1) x axis (1, 0, 0)
  circle C1 centre (-0.34, 4.83) radius 0.35
  circle C2 centre (-0.34, 14.99) radius 0.35
  circle C3 centre (-0.34, 22.61) radius 0.35
  circle C4 centre (-7.96, 20.07) radius 0.35
  circle C5 centre (-7.96, 4.83) radius 0.35
extrude "Extrude2" new body sketch "K1 leads profile" blind 3.5 from offset 6.5 bodies "K1 leads", "K1 leads (1)", "K1 leads (2)", "K1 leads (3)", "K1 leads (4)"
sketch "U2 converter case profile" plane through (0, 0, 0) normal (0, 0, 1) x axis (1, 0, 0)
  line L1 (17.26, 27.81) -> (3.66, 27.81)
  line L2 (17.46, 35.21) -> (17.46, 28.01)
  line L3 (3.66, 35.41) -> (17.26, 35.41)
  line L4 (3.46, 28.01) -> (3.46, 35.21)
  arc A1 centre (17.26, 28.01) radius 0.2 clockwise from (17.46, 28.01) to (17.26, 27.81)
  arc A2 centre (17.26, 35.21) radius 0.2 clockwise from (17.26, 35.41) to (17.46, 35.21)
  arc A3 centre (3.66, 35.21) radius 0.2 clockwise from (3.46, 35.21) to (3.66, 35.41)
  arc A4 centre (3.66, 28.01) radius 0.2 clockwise from (3.66, 27.81) to (3.46, 28.01)
extrude "Extrude1" new body sketch "U2 converter case profile" blind 10.2 from offset 9.1 bodies "U2 converter case"
sketch "U2 leads profile" plane through (0, 0, 0) normal (0, 0, 1) x axis (1, 0, 0)
  circle C1 centre (13, 29.25) radius 0.32
  circle C2 centre (10.46, 29.25) radius 0.32
  circle C3 centre (7.92, 29.25) radius 0.32
extrude "Extrude2" new body sketch "U2 leads profile" blind 3.5 from offset 6.5 bodies "U2 leads", "U2 leads (1)", "U2 leads (2)"
sketch "Q1 insulating support profile" plane through (0, 0, 0) normal (0, 0, 1) x axis (1, 0, 0)
  line L1 (-10.84, -22.855) -> (-20.84, -22.855)
  line L2 (-10.64, -6.855) -> (-10.64, -22.655)
  line L3 (-20.84, -6.655) -> (-10.84, -6.655)
  line L4 (-21.04, -22.655) -> (-21.04, -6.855)
  arc A1 centre (-10.84, -22.655) radius 0.2 clockwise from (-10.64, -22.655) to (-10.84, -22.855)
  arc A2 centre (-10.84, -6.855) radius 0.2 clockwise from (-10.84, -6.655) to (-10.64, -6.855)
  arc A3 centre (-20.84, -6.855) radius 0.2 clockwise from (-21.04, -6.855) to (-20.84, -6.655)
  arc A4 centre (-20.84, -22.655) radius 0.2 clockwise from (-20.84, -22.855) to (-21.04, -22.655)
extrude "Extrude1" new body sketch "Q1 insulating support profile" blind 1 from offset 9.1 bodies "Q1 insulating support"
sketch "Q1 metal tab profile" plane through (0, 0, 0) normal (0, 0, 1) x axis (1, 0, 0)
  line L1 (-10.705, -23.01) -> (-20.975, -23.01)
  line L2 (-10.505, -6.7) -> (-10.505, -22.81)
  line L3 (-20.975, -6.5) -> (-10.705, -6.5)
  line L4 (-21.175, -22.81) -> (-21.175, -6.7)
  arc A1 centre (-10.705, -22.81) radius 0.2 clockwise from (-10.505, -22.81) to (-10.705, -23.01)
  arc A2 centre (-10.705, -6.7) radius 0.2 clockwise from (-10.705, -6.5) to (-10.505, -6.7)
  arc A3 centre (-20.975, -6.7) radius 0.2 clockwise from (-21.175, -6.7) to (-20.975, -6.5)
  arc A4 centre (-20.975, -22.81) radius 0.2 clockwise from (-20.975, -23.01) to (-21.175, -22.81)
extrude "Extrude2" new body sketch "Q1 metal tab profile" blind 0.9 from offset 10.1 bodies "Q1 metal tab"
sketch "Q1 tab screw hole profile" plane through (0, 0, 0) normal (0, 0, 1) x axis (1, 0, 0)
  circle C1 centre (-15.84, -20.03) radius 2.04
extrude "Extrude3" cut sketch "Q1 tab screw hole profile" blind 1 from offset 10.08
sketch "Q1 molded body profile" plane through (0, 0, 0) normal (0, 0, 1) x axis (1, 0, 0)
  line L1 (-10.705, -16.15) -> (-20.975, -16.15)
  line L2 (-10.505, -6.7) -> (-10.505, -15.95)
  line L3 (-20.975, -6.5) -> (-10.705, -6.5)
  line L4 (-21.175, -15.95) -> (-21.175, -6.7)
  arc A1 centre (-10.705, -15.95) radius 0.2 clockwise from (-10.505, -15.95) to (-10.705, -16.15)
  arc A2 centre (-10.705, -6.7) radius 0.2 clockwise from (-10.705, -6.5) to (-10.505, -6.7)
  arc A3 centre (-20.975, -6.7) radius 0.2 clockwise from (-21.175, -6.7) to (-20.975, -6.5)
  arc A4 centre (-20.975, -15.95) radius 0.2 clockwise from (-20.975, -16.15) to (-21.175, -15.95)
extrude "Extrude4" new body sketch "Q1 molded body profile" blind 3.93 from offset 11 bodies "Q1 molded body"
sketch "Q1 bent lead 1 profile" plane through (0, 0, 0) normal (0, 0, 1) x axis (1, 0, 0)
  line L1 (-12.975, -6.5) -> (-13.625, -6.5)
  line L2 (-12.975, -0.5) -> (-12.975, -6.5)
  line L3 (-13.625, -0.5) -> (-12.975, -0.5)
  line L4 (-13.625, -6.5) -> (-13.625, -0.5)
extrude "Extrude5" new body sketch "Q1 bent lead 1 profile" blind 0.5 from offset 11.6 bodies "Q1 bent lead 1"
sketch "Q1 lead tail 1 profile" plane through (0, 0, 0) normal (0, 0, 1) x axis (1, 0, 0)
  circle C1 centre (-13.3, -0.5) radius 0.325
extrude "Extrude6" new body sketch "Q1 lead tail 1 profile" blind 5.8 from offset 6.3 bodies "Q1 lead tail 1"
sketch "Q1 bent lead 2 profile" plane through (0, 0, 0) normal (0, 0, 1) x axis (1, 0, 0)
  line L1 (-15.515, -6.5) -> (-16.165, -6.5)
  line L2 (-15.515, -0.5) -> (-15.515, -6.5)
  line L3 (-16.165, -0.5) -> (-15.515, -0.5)
  line L4 (-16.165, -6.5) -> (-16.165, -0.5)
extrude "Extrude7" new body sketch "Q1 bent lead 2 profile" blind 0.5 from offset 11.6 bodies "Q1 bent lead 2"
sketch "Q1 lead tail 2 profile" plane through (0, 0, 0) normal (0, 0, 1) x axis (1, 0, 0)
  circle C1 centre (-15.84, -0.5) radius 0.325
extrude "Extrude8" new body sketch "Q1 lead tail 2 profile" blind 5.8 from offset 6.3 bodies "Q1 lead tail 2"
sketch "Q1 bent lead 3 profile" plane through (0, 0, 0) normal (0, 0, 1) x axis (1, 0, 0)
  line L1 (-18.055, -6.5) -> (-18.705, -6.5)
  line L2 (-18.055, -0.5) -> (-18.055, -6.5)
  line L3 (-18.705, -0.5) -> (-18.055, -0.5)
  line L4 (-18.705, -6.5) -> (-18.705, -0.5)
extrude "Extrude9" new body sketch "Q1 bent lead 3 profile" blind 0.5 from offset 11.6 bodies "Q1 bent lead 3"
sketch "Q1 lead tail 3 profile" plane through (0, 0, 0) normal (0, 0, 1) x axis (1, 0, 0)
  circle C1 centre (-18.38, -0.5) radius 0.325
extrude "Extrude10" new body sketch "Q1 lead tail 3 profile" blind 5.8 from offset 6.3 bodies "Q1 lead tail 3"
sketch "BZ1 piezo housing profile" plane through (0, 0, 0) normal (0, 0, 1) x axis (1, 0, 0)
  circle C1 centre (23.2, 1.5) radius 6.1
extrude "Extrude1" new body sketch "BZ1 piezo housing profile" blind 7.8 from offset 9.1 bodies "BZ1 piezo housing"
sketch "BZ1 sound opening profile" plane through (0, 0, 0) normal (0, 0, 1) x axis (1, 0, 0)
  circle C1 centre (23.2, 1.5) radius 1.5
extrude "Extrude2" cut sketch "BZ1 sound opening profile" blind 1.22 from offset 15.7
sketch "BZ1 leads profile" plane through (0, 0, 0) normal (0, 0, 1) x axis (1, 0, 0)
  circle C1 centre (25.7, 1.5) radius 0.3
  circle C2 centre (20.7, 1.5) radius 0.3
extrude "Extrude3" new body sketch "BZ1 leads profile" blind 3.5 from offset 6.5 bodies "BZ1 leads", "BZ1 leads (1)"
sketch "J2 RJ45 housing profile" plane through (0, 0, 0) normal (0, 0, 1) x axis (1, 0, 0)
  line L1 (28.175, 37.01) -> (12.825, 37.01)
  line L2 (28.375, 51.8) -> (28.375, 37.21)
  line L3 (12.825, 52) -> (28.175, 52)
  line L4 (12.625, 37.21) -> (12.625, 51.8)
  arc A1 centre (28.175, 37.21) radius 0.2 clockwise from (28.375, 37.21) to (28.175, 37.01)
  arc A2 centre (28.175, 51.8) radius 0.2 clockwise from (28.175, 52) to (28.375, 51.8)
  arc A3 centre (12.825, 51.8) radius 0.2 clockwise from (12.625, 51.8) to (12.825, 52)
  arc A4 centre (12.825, 37.21) radius 0.2 clockwise from (12.825, 37.01) to (12.625, 37.21)
extrude "Extrude1" new body sketch "J2 RJ45 housing profile" blind 13.21 from offset 9.1 bodies "J2 RJ45 housing"
sketch "J2 plug cavity profile" plane through (0, 0, 0) normal (0, 1, 0) x axis (1, 0, 0)
  line L1 (26.2, -11.705) -> (14.8, -11.705)
  line L2 (26.4, -19.505) -> (26.4, -11.905)
  line L3 (14.8, -19.705) -> (26.2, -19.705)
  line L4 (14.6, -11.905) -> (14.6, -19.505)
  arc A1 centre (26.2, -11.905) radius 0.2 clockwise from (26.2, -11.705) to (26.4, -11.905)
  arc A2 centre (26.2, -19.505) radius 0.2 clockwise from (26.4, -19.505) to (26.2, -19.705)
  arc A3 centre (14.8, -19.505) radius 0.2 clockwise from (14.8, -19.705) to (14.6, -19.505)
  arc A4 centre (14.8, -11.905) radius 0.2 clockwise from (14.6, -11.905) to (14.8, -11.705)
extrude "Extrude2" cut sketch "J2 plug cavity profile" blind 3.03 from offset 49
sketch "J2 latch recess profile" plane through (0, 0, 0) normal (0, 1, 0) x axis (1, 0, 0)
  line L1 (22.9, -10.2) -> (18.1, -10.2)
  line L2 (23, -11.6) -> (23, -10.3)
  line L3 (18.1, -11.7) -> (22.9, -11.7)
  line L4 (18, -10.3) -> (18, -11.6)
  arc A1 centre (22.9, -10.3) radius 0.1 clockwise from (22.9, -10.2) to (23, -10.3)
  arc A2 centre (22.9, -11.6) radius 0.1 clockwise from (23, -11.6) to (22.9, -11.7)
  arc A3 centre (18.1, -11.6) radius 0.1 clockwise from (18.1, -11.7) to (18, -11.6)
  arc A4 centre (18.1, -10.3) radius 0.1 clockwise from (18, -10.3) to (18.1, -10.2)
extrude "Extrude3" cut sketch "J2 latch recess profile" blind 2.03 from offset 50
sketch "J2 contact 1 profile" plane through (0, 0, 0) normal (0, 0, 1) x axis (1, 0, 0)
  line L1 (17.035, 49.05) -> (16.765, 49.05)
  line L2 (17.075, 51.51) -> (17.075, 49.09)
  line L3 (16.765, 51.55) -> (17.035, 51.55)
  line L4 (16.725, 49.09) -> (16.725, 51.51)
  arc A1 centre (17.035, 49.09) radius 0.04 clockwise from (17.075, 49.09) to (17.035, 49.05)
  arc A2 centre (17.035, 51.51) radius 0.04 clockwise from (17.035, 51.55) to (17.075, 51.51)
  arc A3 centre (16.765, 51.51) radius 0.04 clockwise from (16.725, 51.51) to (16.765, 51.55)
  arc A4 centre (16.765, 49.09) radius 0.04 clockwise from (16.765, 49.05) to (16.725, 49.09)
extrude "Extrude4" new body sketch "J2 contact 1 profile" blind 0.12 from offset 11.78 bodies "J2 contact 1"
sketch "J2 contact 2 profile" plane through (0, 0, 0) normal (0, 0, 1) x axis (1, 0, 0)
  line L1 (18.055, 49.05) -> (17.785, 49.05)
  line L2 (18.095, 51.51) -> (18.095, 49.09)
  line L3 (17.785, 51.55) -> (18.055, 51.55)
  line L4 (17.745, 49.09) -> (17.745, 51.51)
  arc A1 centre (18.055, 49.09) radius 0.04 clockwise from (18.095, 49.09) to (18.055, 49.05)
  arc A2 centre (18.055, 51.51) radius 0.04 clockwise from (18.055, 51.55) to (18.095, 51.51)
  arc A3 centre (17.785, 51.51) radius 0.04 clockwise from (17.745, 51.51) to (17.785, 51.55)
  arc A4 centre (17.785, 49.09) radius 0.04 clockwise from (17.785, 49.05) to (17.745, 49.09)
extrude "Extrude5" new body sketch "J2 contact 2 profile" blind 0.12 from offset 11.78 bodies "J2 contact 2"
sketch "J2 contact 3 profile" plane through (0, 0, 0) normal (0, 0, 1) x axis (1, 0, 0)
  line L1 (19.075, 49.05) -> (18.805, 49.05)
  line L2 (19.115, 51.51) -> (19.115, 49.09)
  line L3 (18.805, 51.55) -> (19.075, 51.55)
  line L4 (18.765, 49.09) -> (18.765, 51.51)
  arc A1 centre (19.075, 49.09) radius 0.04 clockwise from (19.115, 49.09) to (19.075, 49.05)
  arc A2 centre (19.075, 51.51) radius 0.04 clockwise from (19.075, 51.55) to (19.115, 51.51)
  arc A3 centre (18.805, 51.51) radius 0.04 clockwise from (18.765, 51.51) to (18.805, 51.55)
  arc A4 centre (18.805, 49.09) radius 0.04 clockwise from (18.805, 49.05) to (18.765, 49.09)
extrude "Extrude6" new body sketch "J2 contact 3 profile" blind 0.12 from offset 11.78 bodies "J2 contact 3"
sketch "J2 contact 4 profile" plane through (0, 0, 0) normal (0, 0, 1) x axis (1, 0, 0)
  line L1 (20.095, 49.05) -> (19.825, 49.05)
  line L2 (20.135, 51.51) -> (20.135, 49.09)
  line L3 (19.825, 51.55) -> (20.095, 51.55)
  line L4 (19.785, 49.09) -> (19.785, 51.51)
  arc A1 centre (20.095, 49.09) radius 0.04 clockwise from (20.135, 49.09) to (20.095, 49.05)
  arc A2 centre (20.095, 51.51) radius 0.04 clockwise from (20.095, 51.55) to (20.135, 51.51)
  arc A3 centre (19.825, 51.51) radius 0.04 clockwise from (19.785, 51.51) to (19.825, 51.55)
  arc A4 centre (19.825, 49.09) radius 0.04 clockwise from (19.825, 49.05) to (19.785, 49.09)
